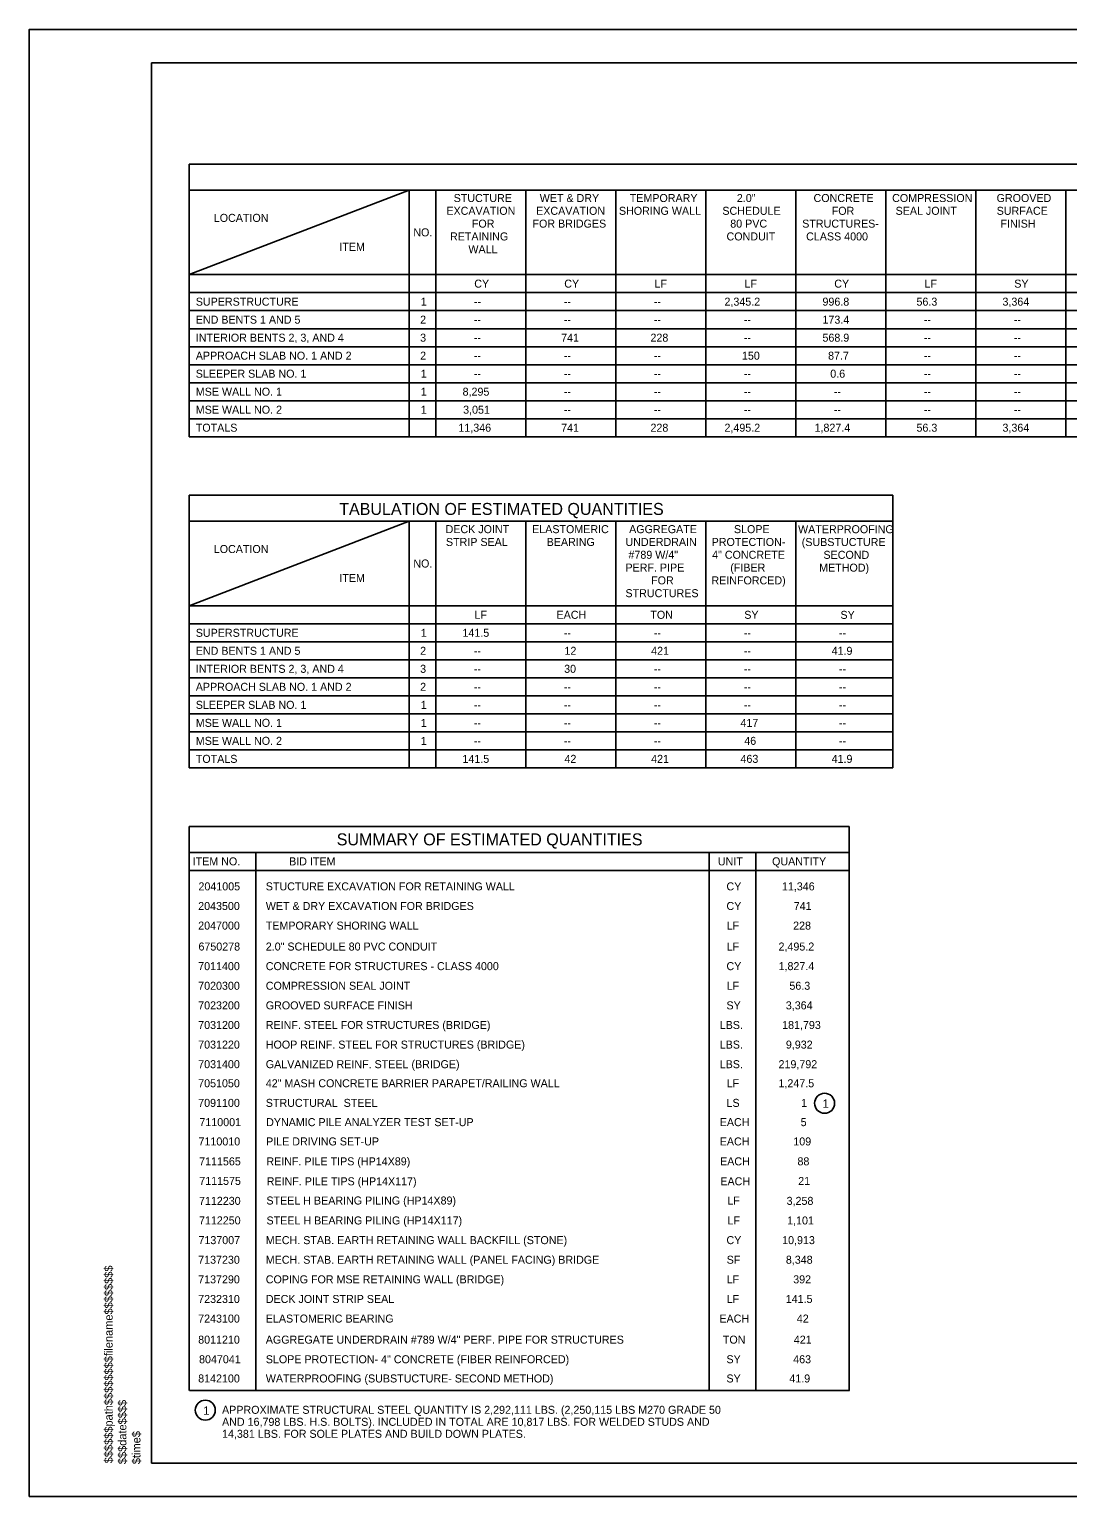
# Model space of a CAD drawing. Extents: x -125.5 to -89.4, y -5.1 to 16.9.
# Drawn here: x -125.53 to -109.96, y -5.07 to 16.93 of the extents above; entities that cross this region are included whole.
import ezdxf

# ---------------------------------------------------------------- set-up
doc = ezdxf.new("R2010")
doc.units = 0
for name, color, linetype in [('BR_BORDER LINES', 7, 'Continuous'), ('BR_TABLE LINES', 7, 'Continuous'), ('BR_TEXT', 7, 'Continuous'), ('Level 31', 7, 'Continuous'), ('RD_SHT_ID', 7, 'Continuous')]:
    doc.layers.add(name, color=color, linetype=linetype)

msp = doc.modelspace()

# ---------------------------------------------------------------- linework, layer by layer
at = {"layer": 'BR_BORDER LINES'}
for p, q in [((-90.033, 16.434), (-123.699, 16.434)), ((-123.699, -4.566), (-123.699, 16.434)), ((-123.699, -4.566), (-90.033, -4.566))]:
    msp.add_line(p, q, dxfattribs=at)
at = {"layer": 'BR_TABLE LINES'}
for p, q in [((-123.136, 14.914), (-90.746, 14.914)), ((-123.136, 14.914), (-123.136, 10.826)), ((-123.136, 14.524), (-90.746, 14.524)), ((-123.136, 13.256), (-119.836, 14.524)), ((-119.836, 14.524), (-119.836, 10.826)), ((-119.436, 14.524), (-119.436, 10.826)), ((-118.086, 14.524), (-118.086, 10.826)), ((-116.736, 14.524), (-116.736, 10.826)), ((-115.386, 14.524), (-115.386, 10.826)), ((-114.036, 14.524), (-114.036, 10.826)), ((-112.686, 14.524), (-112.686, 10.826)), ((-111.336, 14.524), (-111.336, 10.826)), ((-109.986, 14.524), (-109.986, 10.826)), ((-123.136, 13.256), (-90.746, 13.256)), ((-123.136, 12.986), (-90.746, 12.986)), ((-90.746, 12.716), (-123.136, 12.716)), ((-90.746, 12.446), (-123.136, 12.446)), ((-90.746, 12.176), (-123.136, 12.176)), ((-90.746, 11.906), (-123.136, 11.906)), ((-90.746, 11.636), (-123.136, 11.636)), ((-90.746, 11.366), (-123.136, 11.366)), ((-90.746, 11.096), (-123.136, 11.096)), ((-90.746, 10.826), (-123.136, 10.826)), ((-123.136, 9.949), (-123.136, 5.861)), ((-112.58, 9.949), (-123.136, 9.949)), ((-123.136, 9.949), (-112.58, 9.949)), ((-112.58, 9.949), (-112.58, 5.863)), ((-123.136, 9.559), (-112.58, 9.559)), ((-123.136, 8.291), (-119.836, 9.559)), ((-119.836, 9.559), (-119.836, 5.861)), ((-119.436, 9.559), (-119.436, 5.861)), ((-118.086, 9.559), (-118.086, 5.863)), ((-116.736, 9.559), (-116.736, 5.863)), ((-115.386, 9.559), (-115.386, 5.863)), ((-114.036, 9.558), (-114.036, 5.863)), ((-123.136, 8.291), (-112.58, 8.291)), ((-123.136, 8.021), (-112.58, 8.021)), ((-112.58, 7.751), (-123.136, 7.751)), ((-112.58, 7.481), (-123.136, 7.481)), ((-112.58, 7.211), (-123.136, 7.211)), ((-112.58, 6.941), (-123.136, 6.941)), ((-112.58, 6.671), (-123.136, 6.671)), ((-112.58, 6.401), (-123.136, 6.401)), ((-112.58, 6.131), (-123.136, 6.131)), ((-112.58, 5.861), (-123.136, 5.861)), ((-123.136, -3.474), (-123.136, 4.984)), ((-123.136, 4.984), (-113.236, 4.984)), ((-113.236, -3.474), (-113.236, 4.984)), ((-123.136, 4.594), (-113.236, 4.594)), ((-122.136, -3.474), (-122.136, 4.594)), ((-115.336, -3.474), (-115.336, 4.594)), ((-114.636, -3.474), (-114.636, 4.594)), ((-123.136, 4.324), (-113.236, 4.324)), ((-123.131, -3.474), (-113.231, -3.474))]:
    msp.add_line(p, q, dxfattribs=at)
at = {"layer": 'BR_TEXT'}
for centre in [(-113.604, 0.832), (-122.893, -3.769)]:
    msp.add_circle(centre, 0.15, dxfattribs=at)
at = {"layer": 'Level 31'}
msp.add_lwpolyline([(-125.533, -5.066), (-89.533, -5.066), (-89.533, 16.934), (-125.533, 16.934)], close=True, dxfattribs=at)

# ---------------------------------------------------------------- texts
at = {"layer": 'BR_TEXT'}
for s, height, p in [('STUCTURE ', 0.12, (-119.168, 14.345)), ('WET & DRY', 0.12, (-117.877, 14.345)), ('TEMPORARY', 0.12, (-116.527, 14.345)), ('2.0"', 0.12, (-114.92, 14.345)), ('CONCRETE ', 0.12, (-113.77, 14.345)), ('COMPRESSION ', 0.12, (-112.591, 14.345)), ('GROOVED ', 0.12, (-111.024, 14.345)), ('LOCATION', 0.12, (-122.766, 14.047)), ('EXCAVATION ', 0.12, (-119.277, 14.153)), ('FOR ', 0.12, (-118.895, 13.961)), ('FOR BRIDGES', 0.12, (-117.986, 13.961)), ('EXCAVATION', 0.12, (-117.931, 14.153)), ('SHORING WALL', 0.12, (-116.689, 14.153)), (' SCHEDULE', 0.12, (-115.182, 14.153)), ('80 PVC ', 0.12, (-115.019, 13.961)), ('STRUCTURES- ', 0.12, (-113.94, 13.961)), ('FOR ', 0.12, (-113.497, 14.153)), ('SEAL JOINT', 0.12, (-112.539, 14.153)), ('SURFACE ', 0.12, (-111.023, 14.153)), ('FINISH', 0.12, (-110.966, 13.961)), ('NO.', 0.12, (-119.773, 13.83)), ('RETAINING ', 0.12, (-119.223, 13.769)), ('CONDUIT', 0.12, (-115.075, 13.769)), ('CLASS 4000', 0.12, (-113.881, 13.769)), ('ITEM', 0.12, (-120.883, 13.613)), ('WALL', 0.12, (-118.947, 13.577)), ('CY', 0.12, (-118.859, 13.061)), ('CY', 0.12, (-117.509, 13.061)), ('LF', 0.12, (-116.156, 13.061)), ('LF', 0.12, (-114.806, 13.061)), ('CY', 0.12, (-113.459, 13.061)), ('LF', 0.12, (-112.106, 13.061)), ('SY', 0.12, (-110.759, 13.061)), ('SUPERSTRUCTURE', 0.12, (-123.036, 12.791)), ('1', 0.12, (-119.661, 12.791)), ('--', 0.12, (-118.864, 12.791)), ('--', 0.12, (-117.516, 12.791)), ('--', 0.12, (-116.166, 12.791)), ('2,345.2', 0.12, (-115.106, 12.791)), ('996.8', 0.12, (-113.636, 12.791)), ('56.3', 0.12, (-112.226, 12.791)), ('3,364', 0.12, (-110.936, 12.791)), ('END BENTS 1 AND 5', 0.12, (-123.036, 12.521)), ('2', 0.12, (-119.671, 12.521)), ('--', 0.12, (-118.866, 12.521)), ('--', 0.12, (-117.516, 12.521)), ('--', 0.12, (-116.166, 12.521)), ('--', 0.12, (-114.816, 12.521)), ('173.4', 0.12, (-113.636, 12.521)), ('--', 0.12, (-112.116, 12.521)), ('--', 0.12, (-110.766, 12.521)), ('INTERIOR BENTS 2, 3, AND 4', 0.12, (-123.036, 12.251)), ('3', 0.12, (-119.671, 12.251)), ('741', 0.12, (-117.556, 12.251)), ('228', 0.12, (-116.216, 12.251)), ('568.9', 0.12, (-113.636, 12.251)), ('APPROACH SLAB NO. 1 AND 2', 0.12, (-123.036, 11.981)), ('2', 0.12, (-119.671, 11.981)), ('--', 0.12, (-118.866, 12.251)), ('150', 0.12, (-114.844, 11.981)), ('--', 0.12, (-114.816, 12.251)), ('87.7', 0.12, (-113.552, 11.981)), ('--', 0.12, (-112.116, 12.251)), ('--', 0.12, (-110.766, 12.251)), ('--', 0.12, (-118.866, 11.981)), ('--', 0.12, (-117.516, 11.981)), ('--', 0.12, (-116.166, 11.981)), ('--', 0.12, (-112.116, 11.981)), ('--', 0.12, (-110.766, 11.981)), ('SLEEPER SLAB NO. 1', 0.12, (-123.036, 11.711)), ('1', 0.12, (-119.661, 11.711)), ('--', 0.12, (-118.866, 11.711)), ('--', 0.12, (-117.516, 11.711)), ('--', 0.12, (-116.166, 11.711)), ('--', 0.12, (-114.816, 11.711)), ('0.6', 0.12, (-113.519, 11.711)), ('--', 0.12, (-112.116, 11.711)), ('--', 0.12, (-110.766, 11.711)), ('MSE WALL NO. 1', 0.12, (-123.036, 11.441)), ('1', 0.12, (-119.661, 11.441)), ('8,295', 0.12, (-119.034, 11.441)), ('--', 0.12, (-117.516, 11.441)), ('--', 0.12, (-116.166, 11.441)), ('--', 0.12, (-114.816, 11.441)), ('--', 0.12, (-113.466, 11.441)), ('--', 0.12, (-112.116, 11.441)), ('--', 0.12, (-110.766, 11.441)), ('MSE WALL NO. 2', 0.12, (-123.036, 11.171)), ('1', 0.12, (-119.661, 11.171)), ('3,051', 0.12, (-119.026, 11.171)), ('--', 0.12, (-117.516, 11.171)), ('--', 0.12, (-116.166, 11.171)), ('--', 0.12, (-114.816, 11.171)), ('--', 0.12, (-113.466, 11.171)), ('--', 0.12, (-112.116, 11.171)), ('--', 0.12, (-110.766, 11.171)), ('TOTALS', 0.12, (-123.036, 10.901)), ('11,346', 0.12, (-119.097, 10.901)), ('741', 0.12, (-117.556, 10.901)), ('228', 0.12, (-116.216, 10.901)), ('2,495.2', 0.12, (-115.106, 10.901)), ('1,827.4', 0.12, (-113.755, 10.901)), ('56.3', 0.12, (-112.226, 10.901)), ('3,364', 0.12, (-110.936, 10.901)), ('TABULATION OF ESTIMATED QUANTITIES', 0.18, (-120.885, 9.653)), ('DECK JOINT ', 0.12, (-119.289, 9.38)), ('ELASTOMERIC ', 0.12, (-117.991, 9.38)), ('AGGREGATE ', 0.12, (-116.536, 9.38)), ('SLOPE ', 0.12, (-114.964, 9.38)), ('WATERPROOFING ', 0.12, (-114.002, 9.379)), ('STRIP SEAL', 0.12, (-119.284, 9.188)), ('BEARING', 0.12, (-117.773, 9.188)), ('UNDERDRAIN ', 0.12, (-116.591, 9.188)), ('PROTECTION- ', 0.12, (-115.298, 9.188)), ('(SUBSTUCTURE', 0.12, (-113.947, 9.187)), ('LOCATION', 0.12, (-122.766, 9.082)), ('#789 W/4" ', 0.12, (-116.546, 8.996)), ('4" CONCRETE ', 0.12, (-115.291, 8.996)), ('SECOND ', 0.12, (-113.621, 8.995)), ('NO.', 0.12, (-119.773, 8.865)), ('PERF. PIPE ', 0.12, (-116.591, 8.804)), ('(FIBER ', 0.12, (-115.019, 8.804)), ('METHOD)', 0.12, (-113.686, 8.803)), ('ITEM', 0.12, (-120.883, 8.648)), ('FOR ', 0.12, (-116.206, 8.612)), ('REINFORCED)', 0.12, (-115.302, 8.612)), ('STRUCTURES', 0.12, (-116.591, 8.42)), ('LF', 0.12, (-118.856, 8.096)), ('EACH', 0.12, (-117.625, 8.096)), ('TON', 0.12, (-116.218, 8.096)), ('SY', 0.12, (-114.809, 8.096)), ('SY', 0.12, (-113.366, 8.095)), ('SUPERSTRUCTURE', 0.12, (-123.036, 7.826)), ('1', 0.12, (-119.661, 7.826)), ('1', 0.12, (-119.661, 7.826)), ('141.5', 0.12, (-119.036, 7.826)), ('--', 0.12, (-117.516, 7.826)), ('--', 0.12, (-116.166, 7.826)), ('--', 0.12, (-114.816, 7.826)), ('--', 0.12, (-113.388, 7.826)), ('END BENTS 1 AND 5', 0.12, (-123.036, 7.556)), ('2', 0.12, (-119.671, 7.556)), ('--', 0.12, (-118.866, 7.556)), ('12', 0.12, (-117.506, 7.556)), ('421', 0.12, (-116.206, 7.556)), ('--', 0.12, (-114.816, 7.556)), ('41.9', 0.12, (-113.499, 7.556)), ('INTERIOR BENTS 2, 3, AND 4', 0.12, (-123.036, 7.286)), ('3', 0.12, (-119.671, 7.286)), ('--', 0.12, (-118.866, 7.286)), ('30', 0.12, (-117.511, 7.286)), ('--', 0.12, (-116.166, 7.286)), ('--', 0.12, (-114.816, 7.286)), ('--', 0.12, (-113.388, 7.286)), ('APPROACH SLAB NO. 1 AND 2', 0.12, (-123.036, 7.016)), ('2', 0.12, (-119.671, 7.016)), ('--', 0.12, (-118.866, 7.016)), ('--', 0.12, (-117.516, 7.016)), ('--', 0.12, (-116.166, 7.016)), ('--', 0.12, (-114.816, 7.016)), ('--', 0.12, (-113.388, 7.016)), ('SLEEPER SLAB NO. 1', 0.12, (-123.036, 6.746)), ('1', 0.12, (-119.661, 6.746)), ('--', 0.12, (-118.866, 6.746)), ('--', 0.12, (-117.516, 6.746)), ('--', 0.12, (-116.166, 6.746)), ('--', 0.12, (-114.816, 6.746)), ('--', 0.12, (-113.388, 6.746)), ('MSE WALL NO. 1', 0.12, (-123.036, 6.476)), ('1', 0.12, (-119.661, 6.476)), ('--', 0.12, (-118.866, 6.476)), ('--', 0.12, (-117.516, 6.476)), ('--', 0.12, (-116.166, 6.476)), ('417', 0.12, (-114.866, 6.476)), ('--', 0.12, (-113.388, 6.476)), ('MSE WALL NO. 2', 0.12, (-123.036, 6.206)), ('1', 0.12, (-119.661, 6.206)), ('--', 0.12, (-118.866, 6.206)), ('--', 0.12, (-117.516, 6.206)), ('--', 0.12, (-116.166, 6.206)), ('46', 0.12, (-114.809, 6.206)), ('--', 0.12, (-113.388, 6.206)), ('TOTALS', 0.12, (-123.036, 5.936)), ('141.5', 0.12, (-119.036, 5.936)), ('42', 0.12, (-117.506, 5.936)), ('421', 0.12, (-116.206, 5.936)), ('463', 0.12, (-114.866, 5.936)), ('41.9', 0.12, (-113.499, 5.936)), ('SUMMARY OF ESTIMATED QUANTITIES', 0.18, (-120.922, 4.699)), ('ITEM NO.', 0.12, (-123.083, 4.399)), ('BID ITEM', 0.12, (-121.636, 4.399)), ('UNIT', 0.12, (-115.205, 4.399)), ('QUANTITY', 0.12, (-114.392, 4.399)), ('2041005', 0.12, (-122.996, 4.024)), ('STUCTURE EXCAVATION FOR RETAINING WALL', 0.12, (-121.986, 4.024)), ('CY', 0.12, (-115.076, 4.024)), ('11,346', 0.12, (-114.244, 4.024)), ('2043500', 0.12, (-123, 3.73)), ('WET & DRY EXCAVATION FOR BRIDGES', 0.12, (-121.986, 3.73)), ('CY', 0.12, (-115.076, 3.73)), ('741', 0.12, (-114.067, 3.73)), ('2047000', 0.12, (-123, 3.436)), ('TEMPORARY SHORING WALL', 0.12, (-121.986, 3.436)), ('LF', 0.12, (-115.073, 3.436)), ('228', 0.12, (-114.076, 3.436)), ('6750278', 0.12, (-122.996, 3.122)), ('2.0" SCHEDULE 80 PVC CONDUIT', 0.12, (-121.986, 3.122)), ('LF', 0.12, (-115.073, 3.122)), ('2,495.2', 0.12, (-114.295, 3.122)), ('7011400', 0.12, (-123, 2.828)), ('CONCRETE FOR STRUCTURES - CLASS 4000', 0.12, (-121.986, 2.828)), ('CY', 0.12, (-115.076, 2.828)), ('1,827.4', 0.12, (-114.295, 2.828)), ('7020300', 0.12, (-123, 2.534)), ('COMPRESSION SEAL JOINT', 0.12, (-121.986, 2.534)), ('LF', 0.12, (-115.073, 2.534)), ('56.3', 0.12, (-114.132, 2.534)), ('7023200', 0.12, (-123, 2.24)), ('GROOVED SURFACE FINISH', 0.12, (-121.986, 2.24)), ('SY', 0.12, (-115.076, 2.24)), ('3,364', 0.12, (-114.186, 2.24)), ('7031200', 0.12, (-123, 1.946)), ('REINF. STEEL FOR STRUCTURES (BRIDGE)', 0.12, (-121.986, 1.946)), ('LBS.', 0.12, (-115.177, 1.946)), ('181,793', 0.12, (-114.241, 1.946)), ('7031220', 0.12, (-123, 1.652)), ('HOOP REINF. STEEL FOR STRUCTURES (BRIDGE)', 0.12, (-121.986, 1.652)), ('LBS.', 0.12, (-115.177, 1.652)), ('9,932', 0.12, (-114.185, 1.652)), ('7031400', 0.12, (-123, 1.358)), ('GALVANIZED REINF. STEEL (BRIDGE)', 0.12, (-121.986, 1.358)), ('LBS.', 0.12, (-115.177, 1.358)), ('219,792', 0.12, (-114.295, 1.358)), ('7051050', 0.12, (-123, 1.072)), ('42" MASH CONCRETE BARRIER PARAPET/RAILING WALL', 0.12, (-121.986, 1.072)), ('LF', 0.12, (-115.073, 1.072)), ('1,247.5', 0.12, (-114.296, 1.072)), ('7091100', 0.12, (-123, 0.778)), ('STRUCTURAL  STEEL', 0.12, (-121.986, 0.778)), ('LS', 0.12, (-115.075, 0.778)), ('1', 0.12, (-113.956, 0.778)), ('1', 0.125, (-113.635, 0.764)), ('7110001', 0.12, (-122.982, 0.489)), ('DYNAMIC PILE ANALYZER TEST SET-UP', 0.12, (-121.981, 0.489)), ('EACH', 0.12, (-115.177, 0.489)), ('5', 0.12, (-113.963, 0.489)), ('7110010', 0.12, (-122.995, 0.2)), ('PILE DRIVING SET-UP', 0.12, (-121.981, 0.2)), ('EACH', 0.12, (-115.177, 0.2)), ('109', 0.12, (-114.073, 0.2)), ('7111565', 0.12, (-122.986, -0.099)), ('REINF. PILE TIPS (HP14X89)', 0.12, (-121.977, -0.099)), ('EACH', 0.12, (-115.172, -0.099)), ('88', 0.12, (-114.011, -0.099)), ('7111575', 0.12, (-122.984, -0.392)), ('REINF. PILE TIPS (HP14X117)', 0.12, (-121.972, -0.398)), ('EACH', 0.12, (-115.168, -0.398)), ('21', 0.12, (-114, -0.393)), ('7112230', 0.12, (-122.988, -0.691)), ('STEEL H BEARING PILING (HP14X89)', 0.12, (-121.977, -0.686)), ('LF', 0.12, (-115.063, -0.686)), ('3,258', 0.12, (-114.174, -0.691)), ('7112250', 0.12, (-122.988, -0.984)), ('STEEL H BEARING PILING (HP14X117)', 0.12, (-121.975, -0.985)), ('LF', 0.12, (-115.061, -0.985)), ('1,101', 0.12, (-114.166, -0.985)), ('7137007', 0.12, (-122.996, -1.28)), ('MECH. STAB. EARTH RETAINING WALL BACKFILL (STONE)', 0.12, (-121.986, -1.28)), ('CY', 0.12, (-115.076, -1.28)), ('10,913', 0.12, (-114.241, -1.28)), ('7137230', 0.12, (-123, -1.574)), ('MECH. STAB. EARTH RETAINING WALL (PANEL FACING) BRIDGE', 0.12, (-121.986, -1.574)), ('SF', 0.12, (-115.073, -1.574)), ('8,348', 0.12, (-114.185, -1.574)), ('7137290', 0.12, (-123, -1.868)), ('COPING FOR MSE RETAINING WALL (BRIDGE)', 0.12, (-121.986, -1.868)), ('LF', 0.12, (-115.073, -1.868)), ('392', 0.12, (-114.075, -1.868)), ('7232310', 0.12, (-123, -2.162)), ('DECK JOINT STRIP SEAL', 0.12, (-121.986, -2.162)), ('LF', 0.12, (-115.073, -2.162)), ('141.5', 0.12, (-114.187, -2.162)), ('7243100', 0.12, (-123, -2.456)), ('ELASTOMERIC BEARING', 0.12, (-121.986, -2.456)), ('EACH', 0.12, (-115.182, -2.456)), ('42', 0.12, (-114.021, -2.456)), ('8011210', 0.12, (-123, -2.772)), ('AGGREGATE UNDERDRAIN #789 W/4" PERF. PIPE FOR STRUCTURES', 0.12, (-121.986, -2.772)), ('TON', 0.12, (-115.13, -2.772)), ('421', 0.12, (-114.066, -2.772)), ('8047041', 0.12, (-122.987, -3.066)), ('SLOPE PROTECTION- 4" CONCRETE (FIBER REINFORCED)', 0.12, (-121.986, -3.066)), ('SY', 0.12, (-115.076, -3.066)), ('463', 0.12, (-114.075, -3.066)), ('8142100', 0.12, (-123, -3.354)), ('WATERPROOFING (SUBSTUCTURE- SECOND METHOD)', 0.12, (-121.986, -3.354)), ('SY', 0.12, (-115.076, -3.354)), ('41.9', 0.12, (-114.133, -3.354)), ('APPROXIMATE STRUCTURAL STEEL QUANTITY IS 2,292,111 LBS. (2,250,115 LBS M270 GRADE 50', 0.12, (-122.642, -3.824)), ('AND 16,798 LBS. H.S. BOLTS). INCLUDED IN TOTAL ARE 10,817 LBS. FOR WELDED STUDS AND', 0.12, (-122.642, -4.004)), ('14,381 LBS. FOR SOLE PLATES AND BUILD DOWN PLATES.', 0.12, (-122.642, -4.184))]:
    msp.add_text(s, height=height, dxfattribs=at).set_placement(p)
msp.add_text('1', height=0.125, rotation=360, dxfattribs=at).set_placement((-122.925, -3.838))
at = {"layer": 'RD_SHT_ID'}
for s, height, p in [('$$$$$$path$$$$$$$$filename$$$$$$$$', 0.12347, (-124.283, -4.566)), ('$$$date$$$$', 0.12347, (-124.077, -4.579)), ('$time$', 0.1235, (-123.866, -4.579))]:
    msp.add_text(s, height=height, rotation=90, dxfattribs=at).set_placement(p)

doc.saveas('drawing.dxf')
